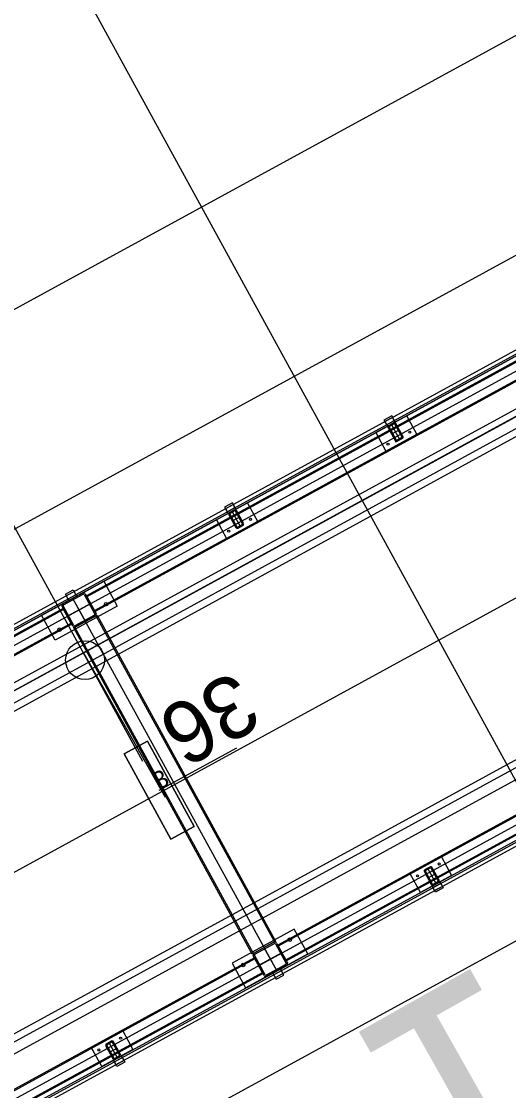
# Model space of a CAD drawing. Extents: x -783978 to -783565, y -1064821 to -1064596.
# Drawn here: x -783756.29 to -783753.54, y -1064678.59 to -1064672.55 of the extents above; entities that cross this region are included whole.
import ezdxf

# ---------------------------------------------------------------- set-up
doc = ezdxf.new("R2010")
doc.units = 0
for name, color, linetype in [('Default', 7, 'Continuous'), ('SO 01_10_01', 7, 'Continuous'), ('SO 01_11_01', 7, 'Continuous'), ('SO 01_20_01', 7, 'Continuous'), ('SO 01_50_01', 7, 'Continuous'), ('SO 01_74_01', 7, 'Continuous'), ('SO 01_86_02', 7, 'Continuous'), ('SO 01_86_04', 7, 'Continuous')]:
    doc.layers.add(name, color=color, linetype=linetype)

# ---------------------------------------------------------------- blocks, each defined once
blk = doc.blocks.new('POINT_DISPLAY')
at = {"layer": 'Default'}
blk.add_line((0, 0), (0, 0), dxfattribs=at)

msp = doc.modelspace()

# ---------------------------------------------------------------- linework, layer by layer
at = {"layer": 'SO 01_10_01'}
msp.add_line((-783746.8769, -1064688.9457), (-783768.5868, -1064649.2609), dxfattribs=at)
at = {"layer": 'SO 01_11_01'}
msp.add_line((-783772.8819, -1064683.2217), (-783730.898, -1064660.279), dxfattribs=at)
at = {"layer": 'SO 01_20_01'}
for p, q in [((-783735.0054, -1064663.7532), (-783787.4671, -1064692.4555)), ((-783735.2041, -1064664.4318), (-783786.7885, -1064692.6541)), ((-783786.6445, -1064692.9173), (-783735.3233, -1064664.839)), ((-783738.0171, -1064666.3812), (-783786.4402, -1064692.874)), ((-783786.421, -1064692.9091), (-783737.9979, -1064666.4163)), ((-783737.8741, -1064667.2605), (-783785.3352, -1064693.2269)), ((-783785.6531, -1064694.3127), (-783737.23, -1064667.82)), ((-783737.0912, -1064667.858), (-783785.7805, -1064694.4964)), ((-783737.2108, -1064667.855), (-783785.6339, -1064694.3478)), ((-783785.6366, -1064694.7596), (-783736.9472, -1064668.1212)), ((-783746.2961, -1064673.8055), (-783785.8354, -1064695.4379))]:
    msp.add_line(p, q, dxfattribs=at)
at = {"layer": 'SO 01_50_01'}
for p, q in [((-783786.7885, -1064692.6541), (-783725.4827, -1064659.1131)), ((-783756.0835, -1064675.8552), (-783751.6971, -1064673.4553)), ((-783756.0835, -1064675.8552), (-783751.6971, -1064673.4554)), ((-783756.0835, -1064675.8552), (-783751.6971, -1064673.4554)), ((-783755.6036, -1064676.7324), (-783756.5635, -1064674.9779)), ((-783760.47, -1064678.255), (-783756.0835, -1064675.8552)), ((-783760.4699, -1064678.2551), (-783756.0835, -1064675.8552)), ((-783760.4699, -1064678.2551), (-783756.0835, -1064675.8552))]:
    msp.add_line(p, q, dxfattribs=at)
at = {"layer": 'SO 01_74_01'}
for p, q in [((-783735.2185, -1064664.4055), (-783786.6099, -1064692.5222)), ((-783786.6003, -1064692.5398), (-783735.2089, -1064664.423)), ((-783785.4388, -1064694.6628), (-783745.8293, -1064672.9921)), ((-783745.8197, -1064673.0096), (-783785.4292, -1064694.6803)), ((-783753.3563, -1064674.3916), (-783755.9224, -1064675.7955)), ((-783753.3533, -1064674.3971), (-783755.9194, -1064675.801)), ((-783755.8774, -1064675.8777), (-783753.3114, -1064674.4738)), ((-783755.8744, -1064675.8832), (-783753.3083, -1064674.4793)), ((-783754.199, -1064674.7785), (-783754.2429, -1064674.8025)), ((-783754.1798, -1064674.8136), (-783754.199, -1064674.7785)), ((-783754.2429, -1064674.8025), (-783754.2237, -1064674.8376)), ((-783754.1942, -1064674.7873), (-783754.2381, -1064674.8113)), ((-783754.2381, -1064674.8113), (-783754.2285, -1064674.8288)), ((-783754.2285, -1064674.8288), (-783754.1846, -1064674.8049)), ((-783754.2237, -1064674.8376), (-783754.1798, -1064674.8136)), ((-783754.1846, -1064674.8049), (-783754.1942, -1064674.7873)), ((-783755.0982, -1064675.2705), (-783755.1421, -1064675.2945)), ((-783755.1421, -1064675.2945), (-783755.1229, -1064675.3296)), ((-783755.0934, -1064675.2793), (-783755.1373, -1064675.3033)), ((-783755.1373, -1064675.3033), (-783755.1277, -1064675.3208)), ((-783755.1277, -1064675.3208), (-783755.0838, -1064675.2968)), ((-783755.1229, -1064675.3296), (-783755.079, -1064675.3056)), ((-783755.079, -1064675.3056), (-783755.0982, -1064675.2705)), ((-783755.0838, -1064675.2968), (-783755.0934, -1064675.2793)), ((-783756.0413, -1064675.7865), (-783755.9975, -1064675.7625)), ((-783756.0221, -1064675.8216), (-783756.0413, -1064675.7865)), ((-783755.9783, -1064675.7976), (-783756.0221, -1064675.8216)), ((-783755.9975, -1064675.7625), (-783755.9783, -1064675.7976)), ((-783755.9224, -1064675.7955), (-783755.8744, -1064675.8832)), ((-783755.9194, -1064675.801), (-783755.8774, -1064675.8777)), ((-783756.054, -1064675.8675), (-783758.62, -1064677.2714)), ((-783756.006, -1064675.9552), (-783756.054, -1064675.8675)), ((-783756.051, -1064675.873), (-783758.617, -1064677.2769)), ((-783756.009, -1064675.9497), (-783756.051, -1064675.873)), ((-783755.994, -1064675.9772), (-783755.8624, -1064675.9052)), ((-783755.987, -1064675.9733), (-783755.8694, -1064675.909)), ((-783755.8694, -1064675.909), (-783754.8615, -1064677.7513)), ((-783755.8624, -1064675.9052), (-783754.8545, -1064677.7475)), ((-783758.5751, -1064677.3536), (-783756.009, -1064675.9497)), ((-783758.572, -1064677.3591), (-783756.006, -1064675.9552)), ((-783754.986, -1064677.8195), (-783755.994, -1064675.9772)), ((-783754.979, -1064677.8156), (-783755.987, -1064675.9733)), ((-783752.2764, -1064676.3655), (-783754.8425, -1064677.7694)), ((-783752.2734, -1064676.371), (-783754.8394, -1064677.7749)), ((-783754.7975, -1064677.8516), (-783752.2314, -1064676.4477)), ((-783754.7945, -1064677.8571), (-783752.2284, -1064676.4532)), ((-783753.971, -1064677.4351), (-783753.9271, -1064677.4111)), ((-783753.9518, -1064677.4702), (-783753.971, -1064677.4351)), ((-783753.9662, -1064677.4438), (-783753.9223, -1064677.4198)), ((-783753.9127, -1064677.4374), (-783753.9566, -1064677.4614)), ((-783753.9271, -1064677.4111), (-783753.9079, -1064677.4462)), ((-783753.9223, -1064677.4198), (-783753.9127, -1064677.4374)), ((-783753.9566, -1064677.4614), (-783753.9662, -1064677.4438)), ((-783753.9079, -1064677.4462), (-783753.9518, -1064677.4702)), ((-783754.8545, -1064677.7475), (-783754.986, -1064677.8195)), ((-783754.8615, -1064677.7513), (-783754.979, -1064677.8156)), ((-783754.8425, -1064677.7694), (-783754.7945, -1064677.8571)), ((-783754.8394, -1064677.7749), (-783754.7975, -1064677.8516)), ((-783754.9741, -1064677.8414), (-783757.5401, -1064679.2453)), ((-783754.971, -1064677.8469), (-783757.5371, -1064679.2508)), ((-783754.9261, -1064677.9291), (-783754.9741, -1064677.8414)), ((-783754.9291, -1064677.9236), (-783754.971, -1064677.8469)), ((-783757.4951, -1064679.3275), (-783754.9291, -1064677.9236)), ((-783754.8263, -1064677.903), (-783754.8702, -1064677.927)), ((-783754.8071, -1064677.9381), (-783754.8263, -1064677.903)), ((-783757.4921, -1064679.333), (-783754.9261, -1064677.9291)), ((-783754.8702, -1064677.927), (-783754.851, -1064677.9621)), ((-783754.851, -1064677.9621), (-783754.8071, -1064677.9381)), ((-783755.7694, -1064678.419), (-783755.7255, -1064678.395)), ((-783755.7646, -1064678.4278), (-783755.7207, -1064678.4038)), ((-783755.7255, -1064678.395), (-783755.7063, -1064678.4301)), ((-783755.7207, -1064678.4038), (-783755.7111, -1064678.4213)), ((-783755.7502, -1064678.4541), (-783755.7694, -1064678.419)), ((-783755.755, -1064678.4453), (-783755.7646, -1064678.4278)), ((-783755.7111, -1064678.4213), (-783755.755, -1064678.4453)), ((-783755.7063, -1064678.4301), (-783755.7502, -1064678.4541))]:
    msp.add_line(p, q, dxfattribs=at)
for points in [[(-783735.1681, -1064664.4976), (-783787.4762, -1064693.1159)], [(-783734.0882, -1064666.4715), (-783786.3963, -1064695.0898)], [(-783754.1881, -1064674.8182), (-783754.2154, -1064674.8331)], [(-783754.2136, -1064674.8429), (-783754.1747, -1064674.914)], [(-783754.1851, -1064674.8237), (-783754.2124, -1064674.8386)], [(-783754.2018, -1064674.8256), (-783754.1538, -1064674.9134)], [(-783754.1419, -1064674.8961), (-783754.1808, -1064674.8249)], [(-783754.1364, -1064674.8931), (-783754.1753, -1064674.8219)], [(-783754.2192, -1064674.8459), (-783754.1802, -1064674.9171)], [(-783754.1558, -1064674.8575), (-783754.1997, -1064674.8815)], [(-783754.1704, -1064674.9153), (-783754.1431, -1064674.9004)], [(-783754.1674, -1064674.9208), (-783754.1401, -1064674.9059)], [(-783755.0873, -1064675.3101), (-783755.1146, -1064675.3251)], [(-783755.0843, -1064675.3157), (-783755.1116, -1064675.3306)], [(-783755.101, -1064675.3176), (-783755.053, -1064675.4053)], [(-783755.0411, -1064675.3881), (-783755.08, -1064675.3169)], [(-783755.0356, -1064675.385), (-783755.0745, -1064675.3139)], [(-783755.1184, -1064675.3379), (-783755.0794, -1064675.409)], [(-783755.1128, -1064675.3349), (-783755.0739, -1064675.406)], [(-783755.055, -1064675.3495), (-783755.0989, -1064675.3735)], [(-783755.0696, -1064675.4073), (-783755.0424, -1064675.3923)], [(-783755.0666, -1064675.4128), (-783755.0393, -1064675.3979)], [(-783756.0555, -1064675.8398), (-783755.9449, -1064675.7793)], [(-783756.0516, -1064675.8468), (-783755.9411, -1064675.7863)], [(-783756.0002, -1064675.8096), (-783754.8483, -1064677.915)], [(-783756.0002, -1064675.8096), (-783755.9282, -1064675.9412)], [(-783755.9356, -1064675.7879), (-783755.8752, -1064675.8985)], [(-783755.9286, -1064675.7841), (-783755.8682, -1064675.8946)], [(-783755.9997, -1064675.9666), (-783756.0602, -1064675.8561)], [(-783755.9927, -1064675.9628), (-783756.0532, -1064675.8522)], [(-783755.8984, -1064675.8394), (-783756.03, -1064675.9114)], [(-783755.8768, -1064675.9039), (-783755.9873, -1064675.9644)], [(-783755.8729, -1064675.9109), (-783755.9835, -1064675.9714)], [(-783754.0144, -1064677.3556), (-783753.9755, -1064677.4268)], [(-783753.9834, -1064677.3279), (-783754.0107, -1064677.3428)], [(-783754.0089, -1064677.3526), (-783753.97, -1064677.4238)], [(-783753.9804, -1064677.3334), (-783754.0077, -1064677.3483)], [(-783753.997, -1064677.3353), (-783753.949, -1064677.4231)], [(-783753.9511, -1064677.3672), (-783753.995, -1064677.3912)], [(-783753.9372, -1064677.4058), (-783753.9761, -1064677.3347)], [(-783753.9316, -1064677.4028), (-783753.9706, -1064677.3316)], [(-783753.9657, -1064677.425), (-783753.9384, -1064677.4101)], [(-783753.9627, -1064677.4305), (-783753.9354, -1064677.4156)], [(-783754.9755, -1064677.8137), (-783754.865, -1064677.7532)], [(-783754.9717, -1064677.8207), (-783754.8611, -1064677.7602)], [(-783754.9203, -1064677.7835), (-783754.8483, -1064677.915)], [(-783754.8557, -1064677.7618), (-783754.7952, -1064677.8724)], [(-783754.8487, -1064677.758), (-783754.7882, -1064677.8685)], [(-783754.9198, -1064677.9405), (-783754.9803, -1064677.83)], [(-783754.9128, -1064677.9367), (-783754.9733, -1064677.8261)], [(-783754.8185, -1064677.8133), (-783754.9501, -1064677.8852)], [(-783754.7968, -1064677.8778), (-783754.9074, -1064677.9383)], [(-783754.793, -1064677.8848), (-783754.9035, -1064677.9453)], [(-783755.8129, -1064678.3396), (-783755.7739, -1064678.4107)], [(-783755.7818, -1064678.3118), (-783755.8091, -1064678.3268)], [(-783755.8073, -1064678.3366), (-783755.7684, -1064678.4077)], [(-783755.7788, -1064678.3174), (-783755.8061, -1064678.3323)], [(-783755.7955, -1064678.3193), (-783755.7475, -1064678.407)], [(-783755.7356, -1064678.3897), (-783755.7745, -1064678.3186)], [(-783755.7301, -1064678.3867), (-783755.769, -1064678.3156)], [(-783755.7495, -1064678.3512), (-783755.7934, -1064678.3752)], [(-783755.7641, -1064678.409), (-783755.7369, -1064678.394)], [(-783755.7611, -1064678.4145), (-783755.7338, -1064678.3996)]]:
    msp.add_lwpolyline(points, dxfattribs=at)
for points in [[(-783754.114, -1064674.7776), (-783754.2895, -1064674.8736), (-783754.2319, -1064674.9789), (-783754.0564, -1064674.8829)], [(-783754.1798, -1064674.8136), (-783754.2237, -1064674.8376), (-783754.1757, -1064674.9254), (-783754.1318, -1064674.9014)], [(-783755.0132, -1064675.2696), (-783755.1887, -1064675.3656), (-783755.1311, -1064675.4709), (-783754.9556, -1064675.3749)], [(-783755.7479, -1064675.8539), (-783756.0988, -1064676.0459), (-783756.1756, -1064675.9056), (-783755.8247, -1064675.7136)], [(-783753.8613, -1064677.3751), (-783754.0368, -1064677.4711), (-783754.0944, -1064677.3658), (-783753.9189, -1064677.2698)], [(-783754.7496, -1064677.6787), (-783755.1005, -1064677.8707), (-783755.0237, -1064678.011), (-783754.6728, -1064677.8191)], [(-783755.6597, -1064678.359), (-783755.8352, -1064678.455), (-783755.8928, -1064678.3497), (-783755.7173, -1064678.2537)]]:
    msp.add_lwpolyline(points, close=True, dxfattribs=at)
for centre, radius in [((-783754.0971, -1064674.871), 0.006), ((-783754.22, -1064674.9382), 0.006), ((-783754.9964, -1064675.363), 0.006), ((-783755.1192, -1064675.4301), 0.006), ((-783755.811, -1064675.8428), 0.01), ((-783756.0742, -1064675.9868), 0.01), ((-783753.9308, -1064677.3105), 0.006), ((-783754.0536, -1064677.3777), 0.006), ((-783754.7743, -1064677.7378), 0.01), ((-783755.0374, -1064677.8818), 0.01), ((-783755.7293, -1064678.2945), 0.006), ((-783755.8521, -1064678.3617), 0.006)]:
    msp.add_circle(centre, radius, dxfattribs=at)
for centre, radius, start, end in [((-783754.2109, -1064674.8414), 0.00945, 118.68349, 208.68349), ((-783754.2109, -1064674.8414), 0.00315, 118.68349, 208.68349), ((-783754.1836, -1064674.8264), 0.00945, 28.68349, 118.68349), ((-783754.1836, -1064674.8264), 0.00315, 28.68349, 118.68349), ((-783754.1447, -1064674.8976), 0.00315, 298.68349, 28.68349), ((-783754.1447, -1064674.8976), 0.00945, 298.68349, 28.68349), ((-783754.1719, -1064674.9125), 0.00945, 208.68349, 298.68349), ((-783754.1719, -1064674.9125), 0.00315, 208.68349, 298.68349), ((-783755.1101, -1064675.3333), 0.00945, 118.68349, 208.68349), ((-783755.0828, -1064675.3184), 0.00945, 28.68349, 118.68349), ((-783755.0828, -1064675.3184), 0.00315, 28.68349, 118.68349), ((-783755.1101, -1064675.3333), 0.00315, 118.68349, 208.68349), ((-783755.0439, -1064675.3896), 0.00315, 298.68349, 28.68349), ((-783755.0439, -1064675.3896), 0.00945, 298.68349, 28.68349), ((-783755.0712, -1064675.4045), 0.00945, 208.68349, 298.68349), ((-783755.0712, -1064675.4045), 0.00315, 208.68349, 298.68349), ((-783755.9392, -1064675.7899), 0.012, 28.68349, 118.68349), ((-783755.9392, -1064675.7899), 0.004, 28.68349, 118.68349), ((-783756.0497, -1064675.8503), 0.012, 118.68349, 208.68349), ((-783756.0497, -1064675.8503), 0.004, 118.68349, 208.68349), ((-783755.8787, -1064675.9004), 0.004, 298.68349, 28.68349), ((-783755.8787, -1064675.9004), 0.012, 298.68349, 28.68349), ((-783755.9892, -1064675.9609), 0.012, 208.68349, 298.68349), ((-783755.9892, -1064675.9609), 0.004, 208.68349, 298.68349), ((-783754.0061, -1064677.3511), 0.00945, 118.68349, 208.68349), ((-783754.0061, -1064677.3511), 0.00315, 118.68349, 208.68349), ((-783753.9789, -1064677.3362), 0.00945, 28.68349, 118.68349), ((-783753.9789, -1064677.3362), 0.00315, 28.68349, 118.68349), ((-783753.9672, -1064677.4222), 0.00945, 208.68349, 298.68349), ((-783753.9672, -1064677.4222), 0.00315, 208.68349, 298.68349), ((-783753.9399, -1064677.4073), 0.00315, 298.68349, 28.68349), ((-783753.9399, -1064677.4073), 0.00945, 298.68349, 28.68349), ((-783754.8592, -1064677.7637), 0.012, 28.68349, 118.68349), ((-783754.8592, -1064677.7637), 0.004, 28.68349, 118.68349), ((-783754.9698, -1064677.8242), 0.012, 118.68349, 208.68349), ((-783754.9698, -1064677.8242), 0.004, 118.68349, 208.68349), ((-783754.7987, -1064677.8743), 0.004, 298.68349, 28.68349), ((-783754.7987, -1064677.8743), 0.012, 298.68349, 28.68349), ((-783754.9093, -1064677.9348), 0.012, 208.68349, 298.68349), ((-783754.9093, -1064677.9348), 0.004, 208.68349, 298.68349), ((-783755.8046, -1064678.335), 0.00945, 118.68349, 208.68349), ((-783755.8046, -1064678.335), 0.00315, 118.68349, 208.68349), ((-783755.7773, -1064678.3201), 0.00945, 28.68349, 118.68349), ((-783755.7773, -1064678.3201), 0.00315, 28.68349, 118.68349), ((-783755.7657, -1064678.4062), 0.00315, 208.68349, 298.68349), ((-783755.7384, -1064678.3913), 0.00315, 298.68349, 28.68349), ((-783755.7384, -1064678.3913), 0.00945, 298.68349, 28.68349), ((-783755.7657, -1064678.4062), 0.00945, 208.68349, 298.68349)]:
    msp.add_arc(centre, radius, start, end, dxfattribs=at)
at = {"layer": 'SO 01_86_04'}
for p, q in [((-783755.9389, -1064676.118), (-783755.4787, -1064676.9327)), ((-783755.5776, -1064676.6166), (-783755.7092, -1064676.6886)), ((-783755.5776, -1064676.6166), (-783755.7092, -1064676.6886)), ((-783755.7092, -1064676.6886), (-783755.5776, -1064676.6166)), ((-783755.7092, -1064676.6886), (-783755.5776, -1064676.6166)), ((-783755.3136, -1064677.0991), (-783755.5776, -1064676.6166)), ((-783755.3136, -1064677.0991), (-783755.5776, -1064676.6166)), ((-783755.5776, -1064676.6166), (-783755.3136, -1064677.0991)), ((-783755.5776, -1064676.6166), (-783755.3136, -1064677.0991)), ((-783755.5114, -1064676.8939), (-783755.0727, -1064676.6539)), ((-783755.7092, -1064676.6886), (-783755.4452, -1064677.1711)), ((-783755.7092, -1064676.6886), (-783755.4452, -1064677.1711)), ((-783755.4452, -1064677.1711), (-783755.7092, -1064676.6886)), ((-783755.4452, -1064677.1711), (-783755.7092, -1064676.6886)), ((-783755.4452, -1064677.1711), (-783755.3136, -1064677.0991)), ((-783755.4452, -1064677.1711), (-783755.3136, -1064677.0991)), ((-783755.3136, -1064677.0991), (-783755.4452, -1064677.1711)), ((-783755.3136, -1064677.0991), (-783755.4452, -1064677.1711))]:
    msp.add_line(p, q, dxfattribs=at)
for points in [[(-783738.3222, -1064666.4797), (-783740.5325, -1064667.689), (-783743.1715, -1064669.1328), (-783745.7538, -1064670.5456), (-783748.4385, -1064672.0145), (-783751.0413, -1064673.4385), (-783753.6847, -1064674.8847), (-783756.3281, -1064676.3309), (-783758.9715, -1064677.7772), (-783761.6149, -1064679.2234), (-783764.2583, -1064680.6696), (-783766.9018, -1064682.1159), (-783769.4633, -1064683.5173), (-783772.109, -1064684.9648), (-783774.7882, -1064686.4306), (-783778.1382, -1064688.2722), (-783783.8139, -1064691.3971), (-783785.747, -1064692.4898)], [(-783747.063, -1064670.9765), (-783746.9575, -1064671.1681), (-783786.6893, -1064692.8619), (-783786.185, -1064693.7636)]]:
    msp.add_lwpolyline(points, dxfattribs=at)
msp.add_circle((-783755.9301, -1064676.1591), 0.1097, dxfattribs=at)

# ---------------------------------------------------------------- block references
at = {"layer": 'SO 01_86_04', "xscale": 0.010000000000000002, "yscale": 0.009999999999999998, "rotation": 28.683491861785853}
for p in [(-783755.5776, -1064676.6166), (-783755.5776, -1064676.6166), (-783755.7092, -1064676.6886), (-783755.7092, -1064676.6886), (-783755.3136, -1064677.0991), (-783755.3136, -1064677.0991), (-783755.4452, -1064677.1711), (-783755.4452, -1064677.1711)]:
    msp.add_blockref('POINT_DISPLAY', p, dxfattribs=at)

# ---------------------------------------------------------------- texts
at = {"layer": 'SO 01_86_02'}
msp.add_text('OS1', height=1.25, rotation=209.44605, dxfattribs=at).set_placement((-783751.5428, -1064676.6544))
at = {"layer": 'SO 01_86_04'}
for s, height, rotation, p in [('36', 0.351, 209.46001, (-783755.0845, -1064676.2119)), ('3', 0.1, 28.68349, (-783755.5114, -1064676.8939))]:
    msp.add_text(s, height=height, rotation=rotation, dxfattribs=at).set_placement(p)

doc.saveas('drawing.dxf')
